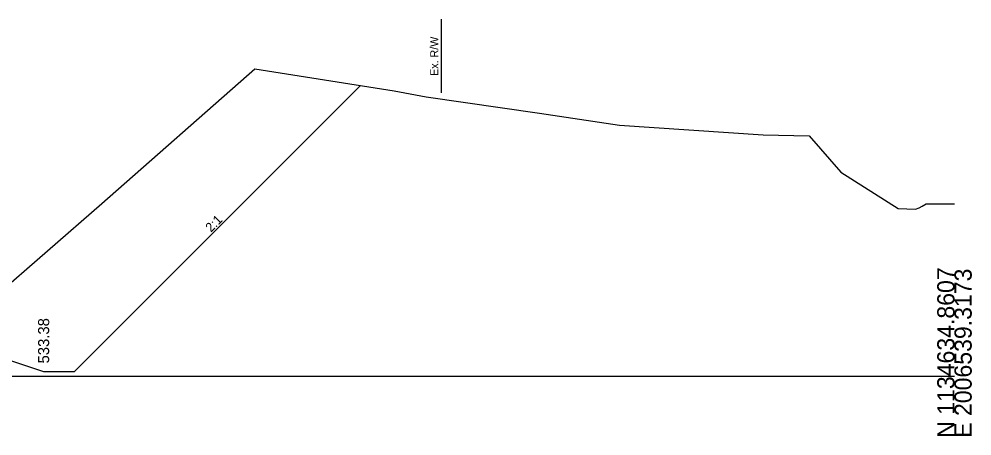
# Model space of a CAD drawing. Extents: x -201 to 2007062, y -213 to 1139737.
# Drawn here: x 1348 to 1502.8, y 1990.3 to 2058 of the extents above; entities that cross this region are included whole.
import ezdxf

# ---------------------------------------------------------------- set-up
doc = ezdxf.new("R2010")
doc.units = 0
for name, color, linetype in [('RD_GPK_XS_Cell', 7, 'Continuous'), ('RD_Sketch1', 7, 'Continuous'), ('RD_XS_ExGround', 7, 'Continuous'), ('RD_XS_ExRW', 7, 'Continuous'), ('RD_XS_TieSlope', 7, 'Continuous'), ('RD_XS_TX_Ditch', 7, 'Continuous'), ('RD_XS_TX_Slope', 7, 'Continuous')]:
    doc.layers.add(name, color=color, linetype=linetype)

msp = doc.modelspace()

# ---------------------------------------------------------------- linework, layer by layer
at = {"layer": 'RD_GPK_XS_Cell'}
msp.add_line((1250, 2000), (1500, 2000), dxfattribs=at)
at = {"layer": 'RD_XS_ExGround'}
msp.add_lwpolyline([(1343.72, 2012.68), (1361.45, 2028.05), (1386.3, 2049.93), (1408.98, 2046.37), (1414.18, 2045.38), (1432.56, 2042.74), (1445.56, 2040.8), (1468.9, 2039.23), (1476.41, 2039.06), (1481.52, 2033.13), (1490.87, 2027.27), (1493.69, 2027.15), (1494.24, 2027.34), (1494.73, 2027.61), (1495.42, 2028), (1497.12, 2028), (1500, 2028)], dxfattribs=at)
at = {"layer": 'RD_XS_ExRW'}
msp.add_line((1416.62, 2058.01), (1416.62, 2046.01), dxfattribs=at)
at = {"layer": 'RD_XS_TieSlope'}
msp.add_lwpolyline([(1328, 2008.77), (1352, 2000.77), (1357, 2000.77), (1403.47, 2047.24)], dxfattribs=at)

# ---------------------------------------------------------------- texts
at = {"layer": 'RD_GPK_XS_Cell'}
for s, p in [('N 1134634.8607', (1500, 1990)), ('E 2006539.3173', (1502.8, 1990))]:
    msp.add_text(s, height=2.8, rotation=90, dxfattribs=at).set_placement(p)
at = {"layer": 'RD_Sketch1'}
for s, p in [('Exterior Boundary', (1402.91, 2047.19)), ('LOC_C', (1403.24, 2047.19)), ('Cut_Ditch', (1351.7, 2000.72)), ('Cut_Ditch1', (1356.67, 2000.72))]:
    msp.add_text(s, height=0.05, dxfattribs=at).set_placement(p)
at = {"layer": 'RD_XS_ExRW'}
msp.add_text('Ex. R/W ', height=1.3, rotation=90, dxfattribs=at).set_placement((1416.12, 2048.78))
at = {"layer": 'RD_XS_TX_Ditch'}
msp.add_text('533.38', height=1.8, rotation=90, dxfattribs=at).set_placement((1352.9, 2002.08))
at = {"layer": 'RD_XS_TX_Slope'}
msp.add_text('2:1', height=1.5, rotation=45, dxfattribs=at).set_placement((1379.19, 2023.31))

doc.saveas('drawing.dxf')
